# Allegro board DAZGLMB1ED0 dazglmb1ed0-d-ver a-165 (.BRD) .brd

Outline 387 x 183 mm; copper layers: TOP, SGND1, IN1, SGND2, IN2, SGND3, SVCC, IN3, SGND4, IN4, SGND5, IN5, SGND6, BOTTOM. Coordinates in mm from the lower left corner of the outline.

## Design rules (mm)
net group DFP-S5(3.1)W5.5(3.5)-T5: nets USBP1+_C USBP1-_C
net group DFP-S7(3.5)W5.5(3.5)-T1B: nets EDP_AUX#_C EDP_AUX_C
net group DFP-S20W5.5(3.5)-T1245B: nets XTAL24_IN XTAL24_OUT
net group W3.1-T12345B: nets H_PROCHOT# LCD_BL_PWM
net group W3.5-T1245B: nets 1080Q_8816AVSNS N35891538
net group W5.5-T12345B: nets BAT-V HP_JD#_EC
net group W80-T12345B: nets +5V_HDD VCC0P9_SVR
net group DFP-S4W5.5(5)-T1245B: nets VMA_CLK0 VMA_CLK0# VMA_CLK1 VMA_CLK1# VMA_WCK01 VMA_WCK01# VMA_WCK23 VMA_WCK23# VMA_WCK45 VMA_WCK45# VMA_WCK67 VMA_WCK67# VMB_CLK0 VMB_CLK0# VMB_CLK1 VMB_CLK1# VMB_WCK01 VMB_WCK01# VMB_WCK23 VMB_WCK23# VMB_WCK45 VMB_WCK45# VMB_WCK67 VMB_WCK67# VMC_CLK0 VMC_CLK0# VMC_CLK1 VMC_CLK1# VMC_WCK01 VMC_WCK01# VMC_WCK23 VMC_WCK23# VMC_WCK45 VMC_WCK45# VMC_WCK67 VMC_WCK67# VMD_CLK0 VMD_CLK0# VMD_CLK1 VMD_CLK1# VMD_WCK01 VMD_WCK01# VMD_WCK23 VMD_WCK23# VMD_WCK45 VMD_WCK45# VMD_WCK67 VMD_WCK67#
net group DFP-S5(3.1)W5.5(3.5)-T1245B: nets C_PCIE_RXN3_C C_PCIE_RXN4_C C_PCIE_RXP3_C C_PCIE_RXP4_C C_PEG_TX0 C_PEG_TX1 C_PEG_TX2 C_PEG_TX3 C_PEG_TX4 C_PEG_TX5 C_PEG_TX6 C_PEG_TX7 C_PEG_TX8 C_PEG_TX9 C_PEG_TX10 C_PEG_TX11 C_PEG_TX12 C_PEG_TX13 C_PEG_TX14 C_PEG_TX15 C_PEG_TX#0 C_PEG_TX#1 C_PEG_TX#2 C_PEG_TX#3 C_PEG_TX#4 C_PEG_TX#5 C_PEG_TX#6 C_PEG_TX#7 C_PEG_TX#8 C_PEG_TX#9 C_PEG_TX#10 C_PEG_TX#11 C_PEG_TX#12 C_PEG_TX#13 C_PEG_TX#14 C_PEG_TX#15 CLK_CPU_BCLKN CLK_CPU_BCLKP CLK_DPLL_NSCCLKN CLK_DPLL_NSCCLKP CLK_PCIE_LANN CLK_PCIE_LANP CLK_PCIE_NGFF1_N CLK_PCIE_NGFF1_N_Q CLK_PCIE_NGFF1_N_RE CLK_PCIE_NGFF1_P CLK_PCIE_NGFF1_P_Q CLK_PCIE_NGFF1_P_RE CLK_PCIE_NGFF2_N CLK_PCIE_NGFF2_N_R CLK_PCIE_NGFF2_N_RE CLK_PCIE_NGFF2_P CLK_PCIE_NGFF2_P_R CLK_PCIE_NGFF2_P_RE CLK_PCIE_TBTN CLK_PCIE_TBTP CLK_VGA_N CLK_VGA_P CPU_EDP_AUXN CPU_EDP_AUXP CPU_EDP_TXN0 CPU_EDP_TXN1 CPU_EDP_TXN2 CPU_EDP_TXN3 CPU_EDP_TXP0 CPU_EDP_TXP1 CPU_EDP_TXP2 CPU_EDP_TXP3 CPU_PCI_BCLKN CPU_PCI_BCLKP CPU_WIGIG_DP_AUXN CPU_WIGIG_DP_AUXP CPU_WIGIG_DP_ML0N CPU_WIGIG_DP_ML0P CPU_WIGIG_DP_ML1N CPU_WIGIG_DP_ML1P CPU_WIGIG_DP_ML2N CPU_WIGIG_DP_ML2P CPU_WIGIG_DP_ML3N CPU_WIGIG_DP_ML3P CPU_WIGIG_PCIE_RXN1 CPU_WIGIG_PCIE_RXP1 CPU_WIGIG_PCIE_TXN1 CPU_WIGIG_PCIE_TXP1 DMI_RXN0 DMI_RXN1 DMI_RXN2 DMI_RXN3 DMI_RXP0 DMI_RXP1 DMI_RXP2 DMI_RXP3 DMI_TXN0 DMI_TXN1 DMI_TXN2 DMI_TXN3 DMI_TXP0 DMI_TXP1 DMI_TXP2 DMI_TXP3 N32090895 N32090898 N35891440 N35891446 N35891554 N35891556 N35952409 N35952413 PCIE9_SATA_RXN PCIE9_SATA_RXN_C PCIE9_SATA_RXN_C_RE_C PCIE9_SATA_RXP PCIE9_SATA_RXP_C PCIE9_SATA_RXP_C_RE_C PCIE9_SATA_TXN PCIE9_SATA_TXN_C PCIE9_SATA_TXN_C_RE PCIE9_SATA_TXN_C_RE_C PCIE9_SATA_TXP PCIE9_SATA_TXP_C PCIE9_SATA_TXP_C_RE PCIE9_SATA_TXP_C_RE_C PCIE10_SATA_RXN PCIE10_SATA_RXN_C PCIE10_SATA_RXN_C_RE PCIE10_SATA_RXN_C_RE_C PCIE10_SATA_RXP PCIE10_SATA_RXP_C PCIE10_SATA_RXP_C_RE PCIE10_SATA_RXP_C_RE_C PCIE10_SATA_TXN PCIE10_SATA_TXN_C PCIE10_SATA_TXN_C_RE PCIE10_SATA_TXN_C_RE_C PCIE10_SATA_TXP PCIE10_SATA_TXP_C PCIE10_SATA_TXP_C_RE PCIE10_SATA_TXP_C_RE_C PCIE11_SATA_RXN PCIE11_SATA_RXN_C PCIE11_SATA_RXN_C_RE PCIE11_SATA_RXN_C_RE_C PCIE11_SATA_RXP PCIE11_SATA_RXP_C PCIE11_SATA_RXP_C_RE PCIE11_SATA_RXP_C_RE_C PCIE11_SATA_TXN PCIE11_SATA_TXN_C PCIE11_SATA_TXN_C_RE PCIE11_SATA_TXN_C_RE_C PCIE11_SATA_TXP PCIE11_SATA_TXP_C PCIE11_SATA_TXP_C_RE PCIE11_SATA_TXP_C_RE_C PCIE12_SATA_RXN PCIE12_SATA_RXN_C PCIE12_SATA_RXN_C_RE PCIE12_SATA_RXN_C_RE_C PCIE12_SATA_RXP PCIE12_SATA_RXP_C PCIE12_SATA_RXP_C_RE PCIE12_SATA_RXP_C_RE_C PCIE12_SATA_TXN PCIE12_SATA_TXN_C PCIE12_SATA_TXN_C_RE PCIE12_SATA_TXN_C_RE_C PCIE12_SATA_TXP PCIE12_SATA_TXP_C PCIE12_SATA_TXP_C_RE PCIE12_SATA_TXP_C_RE_C PCIE13_SATA_RXN PCIE13_SATA_RXN_C PCIE13_SATA_RXN_C_RE PCIE13_SATA_RXN_C_RE_C PCIE13_SATA_RXP PCIE13_SATA_RXP_C PCIE13_SATA_RXP_C_RE PCIE13_SATA_RXP_C_RE_C PCIE13_SATA_TXN PCIE13_SATA_TXN_C PCIE13_SATA_TXN_C_RE PCIE13_SATA_TXN_C_RE_C PCIE13_SATA_TXP PCIE13_SATA_TXP_C PCIE13_SATA_TXP_C_RE PCIE13_SATA_TXP_C_RE_C PCIE14_SATA_RXN PCIE14_SATA_RXN_C PCIE14_SATA_RXN_C_RE PCIE14_SATA_RXN_C_RE_C PCIE14_SATA_RXP PCIE14_SATA_RXP_C PCIE14_SATA_RXP_C_RE PCIE14_SATA_RXP_C_RE_C PCIE14_SATA_TXN PCIE14_SATA_TXN_C PCIE14_SATA_TXN_C_RE PCIE14_SATA_TXN_C_RE_C PCIE14_SATA_TXP PCIE14_SATA_TXP_C PCIE14_SATA_TXP_C_RE PCIE14_SATA_TXP_C_RE_C PCIE15_SATA_RXN PCIE15_SATA_RXN_C PCIE15_SATA_RXN_C_RE PCIE15_SATA_RXN_C_RE_C PCIE15_SATA_RXP PCIE15_SATA_RXP_C PCIE15_SATA_RXP_C_RE PCIE15_SATA_RXP_C_RE_C PCIE15_SATA_TXN PCIE15_SATA_TXN_C PCIE15_SATA_TXN_C_RE PCIE15_SATA_TXN_C_RE_C PCIE15_SATA_TXP PCIE15_SATA_TXP_C PCIE15_SATA_TXP_C_RE PCIE15_SATA_TXP_C_RE_C PCIE16_SATA_RXN PCIE16_SATA_RXN_C PCIE16_SATA_RXN_C_RE PCIE16_SATA_RXN_C_RE_C PCIE16_SATA_RXP PCIE16_SATA_RXP_C PCIE16_SATA_RXP_C_RE PCIE16_SATA_RXP_C_RE_C PCIE16_SATA_TXN PCIE16_SATA_TXN_C PCIE16_SATA_TXN_C_RE PCIE16_SATA_TXN_C_RE_C PCIE16_SATA_TXP PCIE16_SATA_TXP_C PCIE16_SATA_TXP_C_RE PCIE16_SATA_TXP_C_RE_C PCIE_RXN1_TBT_C PCIE_RXN2_TBT PCIE_RXN2_TBT_C PCIE_RXN3_TBT PCIE_RXN3_WLAN PCIE_RXN4_LAN PCIE_RXN4_LAN_R PCIE_RXN4_TBT PCIE_RXP1_TBT_C PCIE_RXP2_TBT PCIE_RXP2_TBT_C PCIE_RXP3_TBT PCIE_RXP3_WLAN PCIE_RXP4_LAN PCIE_RXP4_LAN_R PCIE_RXP4_TBT PCIE_TXN1_TBT PCIE_TXN1_TBT_C PCIE_TXN2_TBT PCIE_TXN2_TBT_C PCIE_TXN3_TBT PCIE_TXN3_TBT_C PCIE_TXN3_WLAN PCIE_TXN3_WLAN_C PCIE_TXN4_LAN PCIE_TXN4_LAN_C PCIE_TXN4_TBT PCIE_TXN4_TBT_C PCIE_TXP1_TBT PCIE_TXP1_TBT_C PCIE_TXP2_TBT PCIE_TXP2_TBT_C PCIE_TXP3_TBT PCIE_TXP3_TBT_C PCIE_TXP3_WLAN PCIE_TXP3_WLAN_C PCIE_TXP4_LAN PCIE_TXP4_LAN_C PCIE_TXP4_TBT PCIE_TXP4_TBT_C PEG_RXN0 PEG_RXN0_C PEG_RXN1 PEG_RXN1_C PEG_RXN2 PEG_RXN2_C PEG_RXN3 PEG_RXN3_C PEG_RXN4 PEG_RXN4_C PEG_RXN5 PEG_RXN5_C PEG_RXN6 PEG_RXN6_C PEG_RXN7 PEG_RXN7_C PEG_RXN8 PEG_RXN8_C PEG_RXN9 PEG_RXN9_C PEG_RXN10 PEG_RXN10_C PEG_RXN11 PEG_RXN11_C PEG_RXN12 PEG_RXN12_C PEG_RXN13 PEG_RXN13_C PEG_RXN14 PEG_RXN14_C PEG_RXN15 PEG_RXN15_C PEG_RXP0 PEG_RXP0_C PEG_RXP1 PEG_RXP1_C PEG_RXP2 PEG_RXP2_C PEG_RXP3 PEG_RXP3_C PEG_RXP4 PEG_RXP4_C PEG_RXP5 PEG_RXP5_C PEG_RXP6 PEG_RXP6_C PEG_RXP7 PEG_RXP7_C PEG_RXP8 PEG_RXP8_C PEG_RXP9 PEG_RXP9_C PEG_RXP10 PEG_RXP10_C PEG_RXP11 PEG_RXP11_C PEG_RXP12 PEG_RXP12_C PEG_RXP13 PEG_RXP13_C PEG_RXP14 PEG_RXP14_C PEG_RXP15 PEG_RXP15_C PEG_TXN0 PEG_TXN1 PEG_TXN2 PEG_TXN3 PEG_TXN4 PEG_TXN5 PEG_TXN6 PEG_TXN7 PEG_TXN8 PEG_TXN9 PEG_TXN10 PEG_TXN11 PEG_TXN12 PEG_TXN13 PEG_TXN14 PEG_TXN15 PEG_TXP0 PEG_TXP1 PEG_TXP2 PEG_TXP3 PEG_TXP4 PEG_TXP5 PEG_TXP6 PEG_TXP7 PEG_TXP8 PEG_TXP9 PEG_TXP10 PEG_TXP11 PEG_TXP12 PEG_TXP13 PEG_TXP14 PEG_TXP15 SATA_RXN0_C SATA_RXP0_C SATA_TXN0_C SATA_TXP0_C TBTA_USB2_D_N TBTA_USB2_D_N_B TBTA_USB2_D_N_T TBTA_USB2_D_P TBTA_USB2_D_P_B TBTA_USB2_D_P_T TBTA_USB2_N_B TBTA_USB2_N_T TBTA_USB2_P_B TBTA_USB2_P_T USB3_RXN1 USB3_RXN2 USB3_RXN2_C USB3_RXN2_C_RE USB3_RXN3 USB3_RXN3_C USB3_RXN3_C_RE USB3_RXN3_C_RE_R USB3_RXP1 USB3_RXP2 USB3_RXP2_C USB3_RXP2_C_RE USB3_RXP3 USB3_RXP3_C USB3_RXP3_C_RE USB3_RXP3_C_RE_R USB3_TXN1 USB3_TXN2 USB3_TXN2_C USB3_TXN2_C_RE USB3_TXN2_C_RE_C USB3_TXN2_C_RE_C_R USB3_TXN3 USB3_TXN3_C USB3_TXN3_C_RE USB3_TXN3_C_RE_C USB3_TXN3_C_RE_C_R USB3_TXP1 USB3_TXP2 USB3_TXP2_C USB3_TXP2_C_RE USB3_TXP2_C_RE_C USB3_TXP2_C_RE_C_R USB3_TXP3 USB3_TXP3_C USB3_TXP3_C_RE USB3_TXP3_C_RE_C USB3_TXP3_C_RE_C_R USBP1+ USBP1- USBP2+ USBP2- USBP3+ USBP3- USBP4+ USBP4- USBP5+ USBP5+_C USBP5- USBP5-_C USBP6+ USBP6- USBP7+ USBP7+_C USBP7- USBP7-_C USBP8+ USBP8+_C USBP8- USBP8-_C USBP9+ USBP9+_R USBP9- USBP9-_R WIGIG_DP_AUXN WIGIG_DP_AUXP WIGIG_PCIE_RXN1 WIGIG_PCIE_RXP1 WIGIG_PCIE_TXN1 WIGIG_PCIE_TXP1
net group DFP-S5W5.5-T: nets USB3_RXN1_R USB3_RXP1_R USB3_TXN1_C USB3_TXN1_R USB3_TXP1_C USB3_TXP1_R USBP1+_C_R USBP1-_C_R USBP2+_R USBP2-_R USBP3+_R USBP3-_R USBP4+_R USBP4-_R WIGIG_DP_ML0N WIGIG_DP_ML0P WIGIG_DP_ML1N WIGIG_DP_ML1P
net group DFP-S5W5.5-TB: nets CLK_PCIE_WIGIGN CLK_PCIE_WIGIGN_C CLK_PCIE_WIGIGP CLK_PCIE_WIGIGP_C CLK_PCIE_WLANN CLK_PCIE_WLANP WIGIG_DP_ML2N WIGIG_DP_ML2P WIGIG_DP_ML3N WIGIG_DP_ML3P
net group DFP-S6(3.1)W5.5(3.5)-T1245B: nets M_A_CLKN0 M_A_CLKN1 M_A_CLKP0 M_A_CLKP1 M_A_DQSN0 M_A_DQSN1 M_A_DQSN2 M_A_DQSN3 M_A_DQSN4 M_A_DQSN5 M_A_DQSN6 M_A_DQSN7 M_A_DQSP0 M_A_DQSP1 M_A_DQSP2 M_A_DQSP3 M_A_DQSP4 M_A_DQSP5 M_A_DQSP6 M_A_DQSP7 M_B_CLKN0 M_B_CLKN1 M_B_CLKP0 M_B_CLKP1 M_B_DQSN0 M_B_DQSN1 M_B_DQSN2 M_B_DQSN3 M_B_DQSN4 M_B_DQSN5 M_B_DQSN6 M_B_DQSN7 M_B_DQSP0 M_B_DQSP1 M_B_DQSP2 M_B_DQSP3 M_B_DQSP4 M_B_DQSP5 M_B_DQSP6 M_B_DQSP7
net group DFP-S7(3.5)W5.5(3.5)-T1245B: nets AUX_SRCN_TBT_C AUX_SRCP_TBT_C C_GPU_TBT_AUXN C_GPU_TBT_AUXP C_GPU_TBT_D0 C_GPU_TBT_D0# C_GPU_TBT_D1 C_GPU_TBT_D1# C_GPU_TBT_D2 C_GPU_TBT_D2# C_GPU_TBT_D3 C_GPU_TBT_D3# C_INT_DP_AUXN C_INT_DP_AUXP C_OUT_DP_TXN0 C_OUT_DP_TXN1 C_OUT_DP_TXN2 C_OUT_DP_TXN3 C_OUT_DP_TXP0 C_OUT_DP_TXP1 C_OUT_DP_TXP2 C_OUT_DP_TXP3 C_OUT_EDP_TXN0 C_OUT_EDP_TXN1 C_OUT_EDP_TXN2 C_OUT_EDP_TXN3 C_OUT_EDP_TXP0 C_OUT_EDP_TXP1 C_OUT_EDP_TXP2 C_OUT_EDP_TXP3 DDI1_TX0_DN DDI1_TX0_DN_C DDI1_TX0_DP DDI1_TX0_DP_C DDI1_TX1_DN DDI1_TX1_DN_C DDI1_TX1_DP DDI1_TX1_DP_C DDI1_TX2_DN DDI1_TX2_DN_C DDI1_TX2_DP DDI1_TX2_DP_C DDI1_TX3_DN DDI1_TX3_DN_C DDI1_TX3_DP DDI1_TX3_DP_C DP_D0 DP_D0# DP_D1 DP_D1# DP_D2 DP_D2# DP_D3 DP_D3# GPU_TBT_AUXN GPU_TBT_AUXP GPU_TBT_D0 GPU_TBT_D0# GPU_TBT_D1 GPU_TBT_D1# GPU_TBT_D2 GPU_TBT_D2# GPU_TBT_D3 GPU_TBT_D3# INT_DP_AUXN INT_DP_AUXP INT_EDP_AUXN INT_EDP_AUXP INT_EDP_TXN0 INT_EDP_TXN0_R INT_EDP_TXN1 INT_EDP_TXN1_R INT_EDP_TXN2 INT_EDP_TXN2_R INT_EDP_TXN3 INT_EDP_TXN3_R INT_EDP_TXP0 INT_EDP_TXP0_R INT_EDP_TXP1 INT_EDP_TXP1_R INT_EDP_TXP2 INT_EDP_TXP2_R INT_EDP_TXP3 INT_EDP_TXP3_R N31931449 N31931452 TBTA_AUX_N TBTA_AUX_P TBTA_DPSRC_AUX_N TBTA_DPSRC_AUX_P TBTA_LSRX TBTA_LSTX TBTA_SBU1 TBTA_SBU2 VGA_XTALIN VGA_XTALOUT
net group DFP-S7W4(3.5)-T1245B: nets GPU_CLK GPU_CLK# GPU_CLK#_C GPU_CLK_C GPU_D0 GPU_D0# GPU_D0#_C GPU_D0_C GPU_D1 GPU_D1# GPU_D1#_C GPU_D1_C GPU_D2 GPU_D2# GPU_D2#_C GPU_D2_C GPU_DDCCLK GPU_DDCDATA HDMI_SCLK HDMI_SDATA LAN_MX0+ LAN_MX0- LAN_MX1+ LAN_MX1- LAN_MX2+ LAN_MX2- LAN_MX3+ LAN_MX3- MDI_0+ MDI_0- MDI_1+ MDI_1- MDI_2+ MDI_2- MDI_3+ MDI_3- TX0_HDMI+ TX0_HDMI- TX1_HDMI+ TX1_HDMI- TX2_HDMI+ TX2_HDMI- TXC_HDMI+ TXC_HDMI-
net group DFP-S7W5.5-T: nets TBTA_CA2HD_1_N TBTA_CA2HD_1_P TBTA_HD2CA_0_N TBTA_HD2CA_0_P TBTA_TX0_N TBTA_TX0_P
net group DFP-S7W5.5-TB: nets EDP_TXN0_C EDP_TXN1_C EDP_TXN2_C EDP_TXN3_C EDP_TXP0_C EDP_TXP1_C EDP_TXP2_C EDP_TXP3_C TBTA_CA2HD_0_N TBTA_CA2HD_0_P TBTA_HD2CA_1_N TBTA_HD2CA_1_P TBTA_TX1_N TBTA_TX1_P
net group DFP-S15W5.5(3.5)-T1245B: nets RTC_X1 RTC_X2 TBT_XTL25_IN TBT_XTL25_OUT XTLI XTLO
net group W5-T1245B: nets FB_CAL_PD_VDDQ FB_CAL_PU_GND FB_CAL_TERM_GND
net group W5-T12345B: nets +VCC3P3_LC +VCCPGPPA +VCCPGPPEF +VCCPGPPG +VCCPRIM_3P3 CLK_VDD CPU_OPC_COMP CPU_OPCE_COMP CPU_OPCE_COMP2 EDP_RCOMP LED_B1_SYS LED_B1_SYS_R LED_B2_BAT LED_B2_BAT_R LED_G1_SYS LED_G1_SYS_R LED_G2_BAT LED_G2_BAT_R LED_G3_M_BTN LED_R1_SYS LED_R1_SYS_R LED_R2_BAT LED_R2_BAT_R PEG_COMP PW_VCC3_ANA_PCIE PW_VCC3_ANA_USB VCC0P9_LVR
net group W5.5(3.5)-T1245B: nets ACZ_BCLK ACZ_RST# ACZ_SDOUT ACZ_SYNC AUD_AZACPU_SCLK AUD_AZACPU_SCLK_R AUD_AZACPU_SDI AUD_AZACPU_SDI_L AUD_AZACPU_SDO AUD_AZACPU_SDO_R CLK_PCI_EC CLK_PCI_EC_R CLK_PCI_LPC CLK_PCI_LPC_R DDR4_DRAMRST# DMIC_CLK DMIC_CLK_C DMIC_DAT DMIC_DATA_C DRAM_RESET# H_CPU_SVIDALRT# H_CPU_SVIDDAT M_A_DQ0 M_A_DQ1 M_A_DQ2 M_A_DQ3 M_A_DQ4 M_A_DQ5 M_A_DQ6 M_A_DQ7 M_A_DQ8 M_A_DQ9 M_A_DQ10 M_A_DQ11 M_A_DQ12 M_A_DQ13 M_A_DQ14 M_A_DQ15 M_A_DQ16 M_A_DQ17 M_A_DQ18 M_A_DQ19 M_A_DQ20 M_A_DQ21 M_A_DQ22 M_A_DQ23 M_A_DQ24 M_A_DQ25 M_A_DQ26 M_A_DQ27 M_A_DQ28 M_A_DQ29 M_A_DQ30 M_A_DQ31 M_A_DQ32 M_A_DQ33 M_A_DQ34 M_A_DQ35 M_A_DQ36 M_A_DQ37 M_A_DQ38 M_A_DQ39 M_A_DQ40 M_A_DQ41 M_A_DQ42 M_A_DQ43 M_A_DQ44 M_A_DQ45 M_A_DQ46 M_A_DQ47 M_A_DQ48 M_A_DQ49 M_A_DQ50 M_A_DQ51 M_A_DQ52 M_A_DQ53 M_A_DQ54 M_A_DQ55 M_A_DQ56 M_A_DQ57 M_A_DQ58 M_A_DQ59 M_A_DQ60 M_A_DQ61 M_A_DQ62 M_A_DQ63 M_B_DQ0 M_B_DQ1 M_B_DQ2 M_B_DQ3 M_B_DQ4 M_B_DQ5 M_B_DQ6 M_B_DQ7 M_B_DQ8 M_B_DQ9 M_B_DQ10 M_B_DQ11 M_B_DQ12 M_B_DQ13 M_B_DQ14 M_B_DQ15 M_B_DQ16 M_B_DQ17 M_B_DQ18 M_B_DQ19 M_B_DQ20 M_B_DQ21 M_B_DQ22 M_B_DQ23 M_B_DQ24 M_B_DQ25 M_B_DQ26 M_B_DQ27 M_B_DQ28 M_B_DQ29 M_B_DQ30 M_B_DQ31 M_B_DQ32 M_B_DQ33 M_B_DQ34 M_B_DQ35 M_B_DQ36 M_B_DQ37 M_B_DQ38 M_B_DQ39 M_B_DQ40 M_B_DQ41 M_B_DQ42 M_B_DQ43 M_B_DQ44 M_B_DQ45 M_B_DQ46 M_B_DQ47 M_B_DQ48 M_B_DQ49 M_B_DQ50 M_B_DQ51 M_B_DQ52 M_B_DQ53 M_B_DQ54 M_B_DQ55 M_B_DQ56 M_B_DQ57 M_B_DQ58 M_B_DQ59 M_B_DQ60 M_B_DQ61 M_B_DQ62 M_B_DQ63 MP2949A_ALT# MP2949A_SCLK MP2949A_SDIO MP2949A_VORTN MP2949A_VORTNA MP2949A_VORTNB MP2949A_VOSEN MP2949A_VOSENA MP2949A_VOSENB N16771972 N31995611 N33795012 N33796046 N33796156 N35891568 PCH_AZ_CODEC_BITCLK PCH_AZ_CODEC_RST# PCH_AZ_CODEC_SDIN0 PCH_AZ_CODEC_SDOUT PCH_AZ_CODEC_SYNC PCIE_CLKREQ1# PCIE_CLKREQ2# PCIE_CLKREQ3# PCIE_CLKREQ4# PCIE_CLKREQ7# PCIE_CLKREQ8# PCIE_CLKREQ_LAN# PCIE_CLKREQ_NGFF1# PCIE_CLKREQ_NGFF2# PCIE_CLKREQ_TBT# PCIE_CLKREQ_TBT#_C PCIE_CLKREQ_VGA# PCIE_CLKREQ_WIGIG# PCIE_CLKREQ_WLAN# PCIE_REQ_LAN#_R RTC_RST# SRTC_RST# VCCIO_VCCSENSE VCCSA_VCCSENSE VCCSA_VSSSENSE VCCSENSE VGT_VCCSENSE VGT_VSSSENSE VR_SVID_ALERT# VR_SVID_CLK VR_SVID_CLK_R VR_SVID_DATA VSSIO_VSSSENSE VSSSENSE WLAN_CLKREQ# XCLK_RBIAS
net group W5.5(3.5: nets 2ND_MBCLK 2ND_MBCLK_THM 2ND_MBDATA 2ND_MBDATA_THM 3ND_MBCLK 3ND_MBCLK_P_KB 3ND_MBCLK_UIF 3ND_MBDATA 3ND_MBDATA_P_KB 3ND_MBDATA_UIF 1006_I2C_SCL 1006_I2C_SDA 1006_I2S_BCLK 1006_I2S_LRCK 1006_I2S_MCLK 1006_I2S_OUT ACE_I2C_SCL2 ACE_I2C_SDA2 BL# BL_ON BLON_EN BLONCON CATERR# CFG_RCOMP CPU_2_PCH_TRIG CPU_2_PCH_TRIG_R CPU_PLTRST#R CPU_THERMDA CPU_THERMDC DDPB_CLK DDPB_DATA DDPC_CLK DDPC_DATA DNBSWON# DP_HPD_PCH DP_HPD_PCH_R EC_PECI EC_PECR_R EC_PWROK EC_PWROK_R EDP_HPD_GPU EDP_HPD_R EDP_HPD_RR EDP_VDD_EN FRM_LCK# FRM_LCK#_PANEL GFX_SCL GFX_SDA GPIO27_IFPE_HPD_Q GPUT_CLK GPUT_DATA H_PM_DOWN H_PM_DOWN_R H_PROCHOT#_R HDMI_HPD HDMI_HPD_PCH HOLD#_7 I2C0_SCL I2C0_SDA I2C1_SCL I2C1_SDA I2C_TP_SCL_R I2C_TP_SDA_R I2CC_SCL_GFX I2CC_SCL_IPC I2CC_SDA_GFX I2CC_SDA_IPC LCD_BLEN LCD_VDD LPC_LAD0 LPC_LAD0_C LPC_LAD1 LPC_LAD1_C LPC_LAD2 LPC_LAD2_C LPC_LAD3 LPC_LAD3_C LPC_LFRAME# MB_THRMTRIP# MBCLK MBDATA MP2949A_VRHOT# N30641967 PCH_2_CPU_TRIG PCH_2_CPU_TRIG_R PCH_BLON_EC PCH_BRIGHT PCH_DISP_ON PCH_DPST_PWM PCH_LVDS_BLON PCH_PECI PCH_PWROK PCH_RSMRST# PCH_SPI_CLK PCH_SPI_CLK_EC PCH_SPI_CS0# PCH_SPI_IO2 PCH_SPI_IO3 PCH_SPI_SI PCH_SPI_SI_EC PCH_SPI_SO PCH_SPI_SO_EC PCH_THRMTRIP_R# PCIE_LAN_WAKE#_R PCIE_WAKE# PCIE_WAKE#_TBT PM_SYNC PM_SYNC_R PM_THRMTRIP# PROCHOT_EC PROCPWRGD ROM_CS ROM_CS_R ROM_SCLK ROM_SCLK_R ROM_SI ROM_SI_R ROM_SO RSMRST# SIO_RCIN# SM_INTRUDER# SMB_ME0_CLK SMB_ME0_DAT SMB_ME1_CLK SMB_ME1_DAT SMB_ME2_CLK SMB_ME2_DAT SMB_ME3_CLK SMB_ME3_DAT SMB_ME4_CLK SMB_ME4_DAT SMB_PCH_CLK SMB_PCH_DAT SMB_RUN_CLK SMB_RUN_DAT SPI_CLK SPI_CS0# SPI_CS0#_UR_ME SPI_HOLD_IO3 SPI_SI SPI_SO SPI_WP_IO2 SYS_PWROK SYS_PWROK_R SYS_RESET# TBT_EE_CLK TBT_EE_CS_N TBT_EE_DI TBT_EE_DO TBT_EE_WP_N TBT_I2C_SCL TBT_I2C_SDA TBT_SPI_HOLD# TPCLK TPDATA USB2_COMP USB_OC0# VCCST_PWRGD VCCST_PWRGD_R WLAN_WAKE_R# WP#_3
net group W5.5-B: nets TBT1_PCIE_RBIAS TBT_RBIAS TBT_RSENSE
net group W6-T12345B: nets +VIN TBTA_LDO_BMC VCC1V8A_TBTA_LDO VCC1V8D_TBTA_LDO VCC3V3_FLASH VCC3V3_TBTA_SX
net group W7-T12345B: nets +3V_DVDD_IO +3V_EDP +3V_TYPEC_DP +3VPCU_EC +601_VCC +602_VCC +603_VCC +604_VCC AVDDL CAP-
net group W8-T1245B: nets 1080Q_FBRTN CORE_PLLVDD FBA_PLL_AVDD FBVDDQ_SENSE N25329172 TBTA_CC1 TBTA_CC2 VGPU_CORE_SENSE VSS_GPU_SENSE
net group W8-T12345B: nets +1.2VSUS +1.8V +1.8V_AON +3V +3V_DEEP_SUS +3V_DVDD +3V_S5 +3V_U3_R +3VPCU +3VPCU_ECPLL +5V_PVDD +5V_TOBII +5VA +A3VPCU +TPVDD AVDDH AVDDVCO CAP+ CCD_PWR DVDDL ECAGND HP-L2 HP-R2 LANVCC MIC2-VREFO-L MIC2-VREFO-R NVVDD USBPWR2 USBPWR3 VCC0P9_DP VCC0P9_PCIE
net group W8.5(5.5)-T1245B: nets FBA_CMD0 FBA_CMD1 FBA_CMD2 FBA_CMD3 FBA_CMD4 FBA_CMD5 FBA_CMD6 FBA_CMD7 FBA_CMD8 FBA_CMD9 FBA_CMD10 FBA_CMD11 FBA_CMD12 FBA_CMD13 FBA_CMD14 FBA_CMD15 FBA_CMD16 FBA_CMD17 FBA_CMD18 FBA_CMD19 FBA_CMD20 FBA_CMD21 FBA_CMD22 FBA_CMD23 FBA_CMD24 FBA_CMD25 FBA_CMD26 FBA_CMD27 FBA_CMD28 FBA_CMD29 FBA_CMD30 FBA_CMD31 FBA_DBI0 FBA_DBI1 FBA_DBI2 FBA_DBI3 FBA_DBI4 FBA_DBI5 FBA_DBI6 FBA_DBI7 FBA_EDC0 FBA_EDC1 FBA_EDC2 FBA_EDC3 FBA_EDC4 FBA_EDC5 FBA_EDC6 FBA_EDC7 FBB_CMD0 FBB_CMD1 FBB_CMD2 FBB_CMD3 FBB_CMD4 FBB_CMD5 FBB_CMD6 FBB_CMD7 FBB_CMD8 FBB_CMD9 FBB_CMD10 FBB_CMD11 FBB_CMD12 FBB_CMD13 FBB_CMD14 FBB_CMD15 FBB_CMD16 FBB_CMD17 FBB_CMD18 FBB_CMD19 FBB_CMD20 FBB_CMD21 FBB_CMD22 FBB_CMD23 FBB_CMD24 FBB_CMD25 FBB_CMD26 FBB_CMD27 FBB_CMD28 FBB_CMD29 FBB_CMD30 FBB_CMD31 FBB_DBI0 FBB_DBI1 FBB_DBI2 FBB_DBI3 FBB_DBI4 FBB_DBI5 FBB_DBI6 FBB_DBI7 FBB_EDC0 FBB_EDC1 FBB_EDC2 FBB_EDC3 FBB_EDC4 FBB_EDC5 FBB_EDC6 FBB_EDC7 FBC_CMD0 FBC_CMD1 FBC_CMD2 FBC_CMD3 FBC_CMD4 FBC_CMD5 FBC_CMD6 FBC_CMD7 FBC_CMD8 FBC_CMD9 FBC_CMD10 FBC_CMD11 FBC_CMD12 FBC_CMD13 FBC_CMD14 FBC_CMD15 FBC_CMD16 FBC_CMD17 FBC_CMD18 FBC_CMD19 FBC_CMD20 FBC_CMD21 FBC_CMD22 FBC_CMD23 FBC_CMD24 FBC_CMD25 FBC_CMD26 FBC_CMD27 FBC_CMD28 FBC_CMD29 FBC_CMD30 FBC_CMD31 FBC_DBI0 FBC_DBI1 FBC_DBI2 FBC_DBI3 FBC_DBI4 FBC_DBI5 FBC_DBI6 FBC_DBI7 FBC_EDC0 FBC_EDC1 FBC_EDC2 FBC_EDC3 FBC_EDC4 FBC_EDC5 FBC_EDC6 FBC_EDC7 FBD_CMD0 FBD_CMD1 FBD_CMD2 FBD_CMD3 FBD_CMD4 FBD_CMD5 FBD_CMD6 FBD_CMD7 FBD_CMD8 FBD_CMD9 FBD_CMD10 FBD_CMD11 FBD_CMD12 FBD_CMD13 FBD_CMD14 FBD_CMD15 FBD_CMD16 FBD_CMD17 FBD_CMD18 FBD_CMD19 FBD_CMD20 FBD_CMD21 FBD_CMD22 FBD_CMD23 FBD_CMD24 FBD_CMD25 FBD_CMD26 FBD_CMD27 FBD_CMD28 FBD_CMD29 FBD_CMD30 FBD_CMD31 FBD_DBI0 FBD_DBI1 FBD_DBI2 FBD_DBI3 FBD_DBI4 FBD_DBI5 FBD_DBI6 FBD_DBI7 FBD_EDC0 FBD_EDC1 FBD_EDC2 FBD_EDC3 FBD_EDC4 FBD_EDC5 FBD_EDC6 FBD_EDC7 M_A_A0 M_A_A1 M_A_A2 M_A_A3 M_A_A4 M_A_A5 M_A_A6 M_A_A7 M_A_A8 M_A_A9 M_A_A10 M_A_A11 M_A_A12 M_A_A13 M_A_ACT# M_A_ALERT# M_A_BA#0 M_A_BA#1 M_A_BG#0 M_A_BG#1 M_A_CAS# M_A_CKE0 M_A_CKE1 M_A_CS#0 M_A_CS#1 M_A_ODT0_CPU M_A_ODT1_CPU M_A_PARITY M_A_RAS# M_A_WE# M_B_A0 M_B_A1 M_B_A2 M_B_A3 M_B_A4 M_B_A5 M_B_A6 M_B_A7 M_B_A8 M_B_A9 M_B_A10 M_B_A11 M_B_A12 M_B_A13 M_B_ACT# M_B_ALERT# M_B_BA#0 M_B_BA#1 M_B_BG#0 M_B_BG#1 M_B_CAS# M_B_CKE0 M_B_CKE1 M_B_CS#0 M_B_CS#1 M_B_ODT0_CPU M_B_ODT1_CPU M_B_PARITY M_B_RAS# M_B_WE# VMA_DQ0 VMA_DQ1 VMA_DQ2 VMA_DQ3 VMA_DQ4 VMA_DQ5 VMA_DQ6 VMA_DQ7 VMA_DQ8 VMA_DQ9 VMA_DQ10 VMA_DQ11 VMA_DQ12 VMA_DQ13 VMA_DQ14 VMA_DQ15 VMA_DQ16 VMA_DQ17 VMA_DQ18 VMA_DQ19 VMA_DQ20 VMA_DQ21 VMA_DQ22 VMA_DQ23 VMA_DQ24 VMA_DQ25 VMA_DQ26 VMA_DQ27 VMA_DQ28 VMA_DQ29 VMA_DQ30 VMA_DQ31 VMA_DQ32 VMA_DQ33 VMA_DQ34 VMA_DQ35 VMA_DQ36 VMA_DQ37 VMA_DQ38 VMA_DQ39 VMA_DQ40 VMA_DQ41 VMA_DQ42 VMA_DQ43 VMA_DQ44 VMA_DQ45 VMA_DQ46 VMA_DQ47 VMA_DQ48 VMA_DQ49 VMA_DQ50 VMA_DQ51 VMA_DQ52 VMA_DQ53 VMA_DQ54 VMA_DQ55 VMA_DQ56 VMA_DQ57 VMA_DQ58 VMA_DQ59 VMA_DQ60 VMA_DQ61 VMA_DQ62 VMA_DQ63 VMB_DQ0 VMB_DQ1 VMB_DQ2 VMB_DQ3 VMB_DQ4 VMB_DQ5 VMB_DQ6 VMB_DQ7 VMB_DQ8 VMB_DQ9 VMB_DQ10 VMB_DQ11 VMB_DQ12 VMB_DQ13 VMB_DQ14 VMB_DQ15 VMB_DQ16 VMB_DQ17 VMB_DQ18 VMB_DQ19 VMB_DQ20 VMB_DQ21 VMB_DQ22 VMB_DQ23 VMB_DQ24 VMB_DQ25 VMB_DQ26 VMB_DQ27 VMB_DQ28 VMB_DQ29 VMB_DQ30 VMB_DQ31 VMB_DQ32 VMB_DQ33 VMB_DQ34 VMB_DQ35 VMB_DQ36 VMB_DQ37 VMB_DQ38 VMB_DQ39 VMB_DQ40 VMB_DQ41 VMB_DQ42 VMB_DQ43 VMB_DQ44 VMB_DQ45 VMB_DQ46 VMB_DQ47 VMB_DQ48 VMB_DQ49 VMB_DQ50 VMB_DQ51 VMB_DQ52 VMB_DQ53 VMB_DQ54 VMB_DQ55 VMB_DQ56 VMB_DQ57 VMB_DQ58 VMB_DQ59 VMB_DQ60 VMB_DQ61 VMB_DQ62 VMB_DQ63 VMC_DQ0 VMC_DQ1 VMC_DQ2 VMC_DQ3 VMC_DQ4 VMC_DQ5 VMC_DQ6 VMC_DQ7 VMC_DQ8 VMC_DQ9 VMC_DQ10 VMC_DQ11 VMC_DQ12 VMC_DQ13 VMC_DQ14 VMC_DQ15 VMC_DQ16 VMC_DQ17 VMC_DQ18 VMC_DQ19 VMC_DQ20 VMC_DQ21 VMC_DQ22 VMC_DQ23 VMC_DQ24 VMC_DQ25 VMC_DQ26 VMC_DQ27 VMC_DQ28 VMC_DQ29 VMC_DQ30 VMC_DQ31 VMC_DQ32 VMC_DQ33 VMC_DQ34 VMC_DQ35 VMC_DQ36 VMC_DQ37 VMC_DQ38 VMC_DQ39 VMC_DQ40 VMC_DQ41 VMC_DQ42 VMC_DQ43 VMC_DQ44 VMC_DQ45 VMC_DQ46 VMC_DQ47 VMC_DQ48 VMC_DQ49 VMC_DQ50 VMC_DQ51 VMC_DQ52 VMC_DQ53 VMC_DQ54 VMC_DQ55 VMC_DQ56 VMC_DQ57 VMC_DQ58 VMC_DQ59 VMC_DQ60 VMC_DQ61 VMC_DQ62 VMC_DQ63 VMD_DQ0 VMD_DQ1 VMD_DQ2 VMD_DQ3 VMD_DQ4 VMD_DQ5 VMD_DQ6 VMD_DQ7 VMD_DQ8 VMD_DQ9 VMD_DQ10 VMD_DQ11 VMD_DQ12 VMD_DQ13 VMD_DQ14 VMD_DQ15 VMD_DQ16 VMD_DQ17 VMD_DQ18 VMD_DQ19 VMD_DQ20 VMD_DQ21 VMD_DQ22 VMD_DQ23 VMD_DQ24 VMD_DQ25 VMD_DQ26 VMD_DQ27 VMD_DQ28 VMD_DQ29 VMD_DQ30 VMD_DQ31 VMD_DQ32 VMD_DQ33 VMD_DQ34 VMD_DQ35 VMD_DQ36 VMD_DQ37 VMD_DQ38 VMD_DQ39 VMD_DQ40 VMD_DQ41 VMD_DQ42 VMD_DQ43 VMD_DQ44 VMD_DQ45 VMD_DQ46 VMD_DQ47 VMD_DQ48 VMD_DQ49 VMD_DQ50 VMD_DQ51 VMD_DQ52 VMD_DQ53 VMD_DQ54 VMD_DQ55 VMD_DQ56 VMD_DQ57 VMD_DQ58 VMD_DQ59 VMD_DQ60 VMD_DQ61 VMD_DQ62 VMD_DQ63
net group W9.84-T12345B: nets FBVDDQ_MEM
net group W10-T1245B: nets DDR_VTT
net group W10-T12345B: nets +1.8V_MAIN +1V_SUS +3V_KB_P +3V_LDO_EC +3V_RTC +5V +5VPCU +5VPD +VCC3P3_S0 +VCC3P3_SX +VCCAPLLEBB +VCCCLK2 +VCCDSW3P3 +VCCPCIE3PLL_1P0 +VCCPGPPBCH +VCCPLL +VCCPLL_OC +VCCPRIM_1.0V_AC17 +VCCPRIM_1.0V_AJ20_AD15 +VCCPRIM_1.0V_AL22 +VIN_VGACORE HP-L3 HP-R3 HPOUT_L2 HPOUT_R2 LED_A_B LED_A_G LED_A_R LED_B4_P_BTN LED_B5_GPU_FAN LED_B5_GPU_FAN_R LED_B_B LED_B_G LED_B_R LED_C_B LED_C_G LED_C_R LED_D_B LED_D_G LED_D_R LED_G4_P_BTN LED_G5_GPU_FAN LED_G5_GPU_FAN_R LED_R4_P_BTN LED_R5_GPU_FAN LED_R5_GPU_FAN_R LX MIC_VCC_1.8V PCIECOMP_N PCIECOMP_P SM_RCOMP_2 TS_PWR TYPEC_VBUS VCC0P9_USB
net group W12-T12345B: nets +3V3PD +5V_TP_RGB SM_RCOMP_0 SM_RCOMP_1
net group W15-T12345B: nets +3V_AR +5V_KB_M +VCCAMPHYPLL_1P0 +VDDQC MIC_JD# VCC0P9_CIO
net group W16-T12345B: nets FBA_VREFC FBB_VREFC FBC_VREFC FBD_VREFC
net group W20-T12345B: nets +1V_GFX +1V_S5 +2.5V +2.5VSUS +3V_EC +3V_MINIDP +5V_FAN1 +5V_FAN2 +5V_GPU_LED +5V_HDMIC +5V_KB_LED +5V_S5 +12V_PANEL +VCC_CORE +VCC_GT +VCC_SA +VCCAMPHY_1P0 +VCCIO +VCCPRIM_1.0V_AJ20 +VCCPRIM_1.0V_AJ20_AA23 +VDDQ +WL_VDD LCDVCC LCDVCC_R LINLVP LIP LVN RINRVP RIP RVN SM_VREF SMDDR_VREF_DQ0_M3 SMDDR_VREF_DQ1_M3 SPKLN_L SPKLP_L SPKRN_L SPKRP_L VREF_CA_DIMM0 VREF_CA_DIMM1
net group W24-T12345B: nets LAN_MCT0 LAN_MCT1 LAN_MCT2 LAN_MCT3
net group W30-T12345B: nets TERM9
net group W40-T12345B: nets +3V_SSD1 +3V_SSD2 L_SPK+ L_SPK- MIC2-L MIC2-L_1 MIC2-R MIC2-R_1 R_SPK+ R_SPK- USBPWR0
net group W80-T: nets VCC0P9_SVR_IND

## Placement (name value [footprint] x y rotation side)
C85  0.1u/10V_2  [C0201]  272.05 125.7 90 top
C194  10u/6.3V_4  [C0402_2]  252.62 119.98 0 bottom
C202  1u/6.3V_2  [C0201]  258.72 114.7 180 bottom
C216  *220p/50V_4  [C0402]  325.27 77.44 90 top
C218  *220p/50V_4  [C0402]  326.38 77.44 90 top
C260  1u/6.3V_2  [C0201]  228.9 126.81 180 bottom
C273  1u/6.3V_2  [C0201]  227.73 126.51 270 bottom
C417  0.1u/10V_2  [C0201]  211.35 103.85 270 bottom
C420  *0.1u/10V_2  [C0201]  211.55 98.87 0 bottom
C574  10u/6.3V_4  [C0402_2]  190.95 55.49 0 bottom
C669  *HDD@47u/6.3V_8  [C0805]  68.52 34.41 180 top
C670  HDD@10u/6.3V_4  [C0402_2]  68.02 32.2 90 bottom
C675  HDD@0.01u/50V_4  [C0402]  70.38 32.3 90 bottom
C680  *HDD@0.1u/16V_4  [C0402]  69.27 32.31 90 bottom
C689  *HDD@0.1u/16V_4  [C0402]  67.84 35.4 270 bottom
C718  10u/6.3V_4  [C0402_2]  358.67 60.93 90 top
C721  1u/6.3V_2  [C0201]  347.85 52.8 180 bottom
C755  0.1u/10V_2  [C0201]  272.84 131.26 180 top
C767  10u/6.3V_4  [C0402_2]  233.95 117.9 180 bottom
C802  *47p/25V_2  [C0201]  269.13 131.79 0 top
C807  47p/25V_2  [C0201]  269.26 127.55 0 top
C812  *0.1u/10V_2  [C0201]  213.68 101.87 270 bottom
C853  *0.1u/10V_2  [C0201]  175.41 68.04 0 top
C887  *180p/50V_4  [C0402]  191.69 60.52 180 bottom
C889  1u/6.3V_2  [C0201]  178.81 61.43 270 bottom
C890  *10p/50V_4  [C0402]  183.66 60.65 0 bottom
C891  0.1u/10V_2  [C0201]  177.95 61.28 90 bottom
C892  0.1u/10V_2  [C0201]  176.3 62.07 90 top
C897  0.1u/10V_2  [C0201]  188.62 69.56 270 top
C961  0.47u/25V_4  [C0402]  382.54 41.75 90 bottom
C963  *22u/25V_8  [C0805]  369.21 36.16 0 top
C1194  0.22u/6.3V_2  [C0201]  219.86 127.85 0 top
C13391  0.22u/6.3V_2  [C0201]  357.91 51.4 180 bottom
C13393  47u/6.3V_6  [C0603]  358.01 62.7 180 top
C13512  10p/50V_4  [C0402]  355.37 45.33 0 top
C13548  0.1u/10V_2  [C0201]  341.78 56.1 180 top
C93687  0.1u/10V_2  [C0201]  330.32 58.51 0 top
C93696  10u/6.3V_4  [C0402_2]  330.6 60.42 90 top
C94044  1u/6.3V_2  [C0201]  350.41 51.02 90 bottom
C94051  *SUB@680p/50V_4  [C0402]  38.37 36.75 270 bottom
C94182  0.1u/10V_2  [C0201]  338.2 68.67 180 bottom
C94248  0.22u/6.3V_2  [C0201]  219.86 127.09 0 top
C94249  0.22u/6.3V_2  [C0201]  219.98 125.44 0 top
C94250  0.22u/6.3V_2  [C0201]  219.98 126.2 0 top
C94251  0.22u/6.3V_2  [C0201]  218.21 125.7 0 top
C94252  0.22u/6.3V_2  [C0201]  218.21 124.93 0 top
C94253  0.22u/6.3V_2  [C0201]  218.59 123.41 0 top
C94254  0.22u/6.3V_2  [C0201]  218.59 124.17 0 top
C94255  0.22u/6.3V_2  [C0201]  217.19 123.41 0 top
C94256  0.22u/6.3V_2  [C0201]  217.19 122.65 0 top
C94257  0.22u/6.3V_2  [C0201]  217.19 121.12 0 top
C94258  0.22u/6.3V_2  [C0201]  217.19 121.89 0 top
C94259  0.22u/6.3V_2  [C0201]  218.49 121 0 top
C94260  0.22u/6.3V_2  [C0201]  218.49 120.23 0 top
C94261  0.22u/6.3V_2  [C0201]  218.49 118.71 0 top
C94262  0.22u/6.3V_2  [C0201]  218.49 119.47 0 top
C94263  0.22u/6.3V_2  [C0201]  218.46 117.19 0 top
C94264  0.22u/6.3V_2  [C0201]  218.46 117.95 0 top
C94265  0.22u/6.3V_2  [C0201]  215.67 116.93 0 top
C94266  0.22u/6.3V_2  [C0201]  215.67 117.69 0 top
C94267  0.22u/6.3V_2  [C0201]  216.68 115.41 270 top
C94268  0.22u/6.3V_2  [C0201]  217.44 115.41 270 top
C94269  0.22u/6.3V_2  [C0201]  215.54 114.9 0 top
C94270  0.22u/6.3V_2  [C0201]  215.54 115.66 0 top
C94271  0.22u/6.3V_2  [C0201]  215.54 113.38 0 top
C94272  0.22u/6.3V_2  [C0201]  215.54 114.14 0 top
C94273  0.22u/6.3V_2  [C0201]  215.54 111.85 0 top
C94274  0.22u/6.3V_2  [C0201]  215.54 112.61 0 top
C94275  0.22u/6.3V_2  [C0201]  214.27 110.94 0 top
C94276  0.22u/6.3V_2  [C0201]  214.27 111.7 0 top
C94277  0.22u/6.3V_2  [C0201]  214.29 109.36 0 top
C94278  0.22u/6.3V_2  [C0201]  214.29 110.13 0 top
C94279  1u/6.3V_2  [C0201]  249.96 114.34 0 bottom
C94280  1u/6.3V_2  [C0201]  255.93 119.85 0 bottom
C94281  1u/6.3V_2  [C0201]  258.72 116.81 180 bottom
C94282  1u/6.3V_2  [C0201]  252.62 114.39 180 bottom
C94283  1u/6.3V_2  [C0201]  258.72 119.09 180 bottom
C94284  1u/6.3V_2  [C0201]  255.93 114.85 0 bottom
C94285  1u/6.3V_2  [C0201]  255.93 118.33 0 bottom
C94286  1u/6.3V_2  [C0201]  258.72 112.61 180 bottom
C94287  1u/6.3V_2  [C0201]  258.72 118.33 180 bottom
C94288  1u/6.3V_2  [C0201]  255.93 114.09 0 bottom
C94289  1u/6.3V_2  [C0201]  255.93 119.09 0 bottom
C94290  1u/6.3V_2  [C0201]  258.72 113.99 180 bottom
C94291  1u/6.3V_2  [C0201]  258.72 119.85 180 bottom
C94292  1u/6.3V_2  [C0201]  249.96 115.1 0 bottom
C94293  1u/6.3V_2  [C0201]  249.58 126.2 0 bottom
C94294  1u/6.3V_2  [C0201]  252.62 115.15 180 bottom
C94295  1u/6.3V_2  [C0201]  258.72 117.57 180 bottom
C94296  1u/6.3V_2  [C0201]  258.72 120.62 180 bottom
C94297  1u/6.3V_2  [C0201]  255.93 120.62 0 bottom
C94298  1u/6.3V_2  [C0201]  252.62 126.08 180 bottom
C94299  10u/6.3V_4  [C0402_2]  258.67 115.66 0 bottom
C94300  10u/6.3V_4  [C0402_2]  255.93 123.41 180 bottom
C94301  10u/6.3V_4  [C0402_2]  255.93 121.76 180 bottom
C94302  10u/6.3V_4  [C0402_2]  249.58 125.19 180 bottom
C94303  10u/6.3V_4  [C0402_2]  252.62 121.25 0 bottom
C94304  10u/6.3V_4  [C0402_2]  255.93 125.06 180 bottom
C94305  10u/6.3V_4  [C0402_2]  258.72 125.06 0 bottom
C94306  10u/6.3V_4  [C0402_2]  252.62 125.06 0 bottom
C94307  10u/6.3V_4  [C0402_2]  252.62 116.17 0 bottom
C94308  10u/6.3V_4  [C0402_2]  252.6 117.49 0 bottom
C94309  10u/6.3V_4  [C0402_2]  252.62 122.52 0 bottom
C94310  10u/6.3V_4  [C0402_2]  255.93 117.19 180 bottom
C94311  10u/6.3V_4  [C0402_2]  255.93 115.92 180 bottom
C94317  10u/6.3V_4  [C0402_2]  252.62 118.71 0 bottom
C94318  10u/6.3V_4  [C0402_2]  252.62 123.79 0 bottom
C94319  22u/6.3V_6  [C0603]  249.58 122.17 180 bottom
C94320  22u/6.3V_6  [C0603]  249.58 117.69 180 bottom
C94321  22u/6.3V_6  [C0603]  258.72 123.41 0 bottom
C94322  22u/6.3V_6  [C0603]  258.72 121.76 0 bottom
C94323  22u/6.3V_6  [C0603]  249.58 120.74 180 bottom
C94324  22u/6.3V_6  [C0603]  249.58 119.22 180 bottom
C94325  22u/6.3V_6  [C0603]  249.58 123.84 180 bottom
C94326  22u/6.3V_6  [C0603]  249.58 116.17 180 bottom
C94384  10u/6.3V_4  [C0402_2]  236.11 126.71 0 bottom
C94385  10u/6.3V_4  [C0402_2]  236.11 125.44 0 bottom
C94386  10u/6.3V_4  [C0402_2]  236.11 122.9 0 bottom
C94387  10u/6.3V_4  [C0402_2]  241.32 117.34 0 bottom
C94388  10u/6.3V_4  [C0402_2]  236.11 124.17 0 bottom
C94389  10u/6.3V_4  [C0402_2]  238.78 113.5 180 bottom
C94390  10u/6.3V_4  [C0402_2]  233.95 121.71 180 bottom
C94391  10u/6.3V_4  [C0402_2]  233.95 120.44 180 bottom
C94392  10u/6.3V_4  [C0402_2]  233.95 119.22 180 bottom
C94393  10u/6.3V_4  [C0402_2]  233.95 122.98 180 bottom
C94394  10u/6.3V_4  [C0402_2]  233.95 126.71 180 bottom
C94395  10u/6.3V_4  [C0402_2]  236.11 121.63 0 bottom
C94396  10u/6.3V_4  [C0402_2]  236.11 119.17 0 bottom
C94397  10u/6.3V_4  [C0402_2]  236.11 116.68 0 bottom
C94398  10u/6.3V_4  [C0402_2]  236.11 120.39 0 bottom
C94399  10u/6.3V_4  [C0402_2]  233.95 124.17 180 bottom
C94400  10u/6.3V_4  [C0402_2]  241.32 116.07 0 bottom
C94401  10u/6.3V_4  [C0402_2]  241.32 113.58 0 bottom
C94402  10u/6.3V_4  [C0402_2]  241.32 118.61 0 bottom
C94403  10u/6.3V_4  [C0402_2]  233.95 116.6 180 bottom
C94404  10u/6.3V_4  [C0402_2]  234.59 114.14 180 bottom
C94405  10u/6.3V_4  [C0402_2]  233.95 125.44 180 bottom
C94406  10u/6.3V_4  [C0402_2]  234.59 112.87 180 bottom
C94407  10u/6.3V_4  [C0402_2]  236.11 117.95 0 bottom
C94408  10u/6.3V_4  [C0402_2]  236.11 115.41 0 bottom
C94409  10u/6.3V_4  [C0402_2]  233.95 115.33 180 bottom
C94410  10u/6.3V_4  [C0402_2]  241.32 114.8 0 bottom
C94411  22u/6.3V_6  [C0603]  238.78 122.52 180 bottom
C94412  22u/6.3V_6  [C0603]  238.75 125.57 180 bottom
C94413  22u/6.3V_6  [C0603]  238.78 121 180 bottom
C94414  22u/6.3V_6  [C0603]  238.78 116.42 180 bottom
C94415  22u/6.3V_6  [C0603]  238.78 114.9 180 bottom
C94416  22u/6.3V_6  [C0603]  238.78 117.95 180 bottom
C94417  22u/6.3V_6  [C0603]  238.75 124.04 180 bottom
C94418  22u/6.3V_6  [C0603]  238.78 119.47 180 bottom
C94423  47u/6.3V_8  [C0805]  244.42 134.99 0 top
C94424  47u/6.3V_8  [C0805]  247.72 135.02 180 top
C94425  47u/6.3V_8  [C0805]  244.42 137.02 0 top
C94426  47u/6.3V_8  [C0805]  247.72 137.18 180 top
C94432  1u/6.3V_2  [C0201]  246.53 121.66 0 bottom
C94433  1u/6.3V_2  [C0201]  243.23 126.1 0 bottom
C94434  1u/6.3V_2  [C0201]  243.23 118.48 0 bottom
C94435  1u/6.3V_2  [C0201]  233.32 112.61 270 bottom
C94436  1u/6.3V_2  [C0201]  243.23 117.72 0 bottom
C94437  1u/6.3V_2  [C0201]  236.01 114.44 180 bottom
C94438  1u/6.3V_2  [C0201]  243.23 115.43 0 bottom
C94439  1u/6.3V_2  [C0201]  243.23 124.58 0 bottom
C94440  1u/6.3V_2  [C0201]  241.19 124.25 180 bottom
C94441  1u/6.3V_2  [C0201]  244.88 114.77 180 bottom
C94442  1u/6.3V_2  [C0201]  243.23 125.34 0 bottom
C94443  1u/6.3V_2  [C0201]  241.19 124.96 180 bottom
C94444  1u/6.3V_2  [C0201]  246.53 122.42 0 bottom
C94445  1u/6.3V_2  [C0201]  246.53 114.8 0 bottom
C94446  1u/6.3V_2  [C0201]  244.88 121.63 180 bottom
C94447  1u/6.3V_2  [C0201]  246.53 126.99 0 bottom
C94448  1u/6.3V_2  [C0201]  246.53 113.25 0 bottom
C94449  1u/6.3V_2  [C0201]  241.19 126.48 180 bottom
C94450  1u/6.3V_2  [C0201]  236.04 113.71 180 bottom
C94451  1u/6.3V_2  [C0201]  246.53 118.61 0 bottom
C94452  1u/6.3V_2  [C0201]  246.53 124.71 0 bottom
C94453  1u/6.3V_2  [C0201]  243.23 122.29 0 bottom
C94454  1u/6.3V_2  [C0201]  246.53 116.32 0 bottom
C94455  1u/6.3V_2  [C0201]  236.04 113 180 bottom
C94456  1u/6.3V_2  [C0201]  244.88 117.06 180 bottom
C94457  1u/6.3V_2  [C0201]  244.88 116.3 180 bottom
C94458  1u/6.3V_2  [C0201]  241.19 123.49 180 bottom
C94459  1u/6.3V_2  [C0201]  246.53 120.9 0 bottom
C94460  1u/6.3V_2  [C0201]  243.23 120.77 0 bottom
C94461  1u/6.3V_2  [C0201]  246.53 117.85 0 bottom
C94462  1u/6.3V_2  [C0201]  243.23 123.05 0 bottom
C94463  1u/6.3V_2  [C0201]  243.23 116.96 0 bottom
C94464  1u/6.3V_2  [C0201]  244.88 118.58 180 bottom
C94465  1u/6.3V_2  [C0201]  244.88 123.94 180 bottom
C94466  1u/6.3V_2  [C0201]  244.88 123.16 180 bottom
C94467  1u/6.3V_2  [C0201]  243.23 119.24 0 bottom
C94468  1u/6.3V_2  [C0201]  244.88 120.11 180 bottom
C94469  1u/6.3V_2  [C0201]  243.23 120.01 0 bottom
C94470  1u/6.3V_2  [C0201]  246.53 123.18 0 bottom
C94471  1u/6.3V_2  [C0201]  246.53 117.09 0 bottom
C94472  1u/6.3V_2  [C0201]  246.53 114.04 0 bottom
C94473  1u/6.3V_2  [C0201]  244.88 120.87 180 bottom
C94474  1u/6.3V_2  [C0201]  244.88 117.82 180 bottom
C94475  1u/6.3V_2  [C0201]  243.23 113.91 0 bottom
C94476  1u/6.3V_2  [C0201]  241.19 125.72 180 bottom
C94477  1u/6.3V_2  [C0201]  244.88 115.54 180 bottom
C94478  1u/6.3V_2  [C0201]  244.88 119.35 180 bottom
C94479  1u/6.3V_2  [C0201]  246.53 125.47 0 bottom
C94480  1u/6.3V_2  [C0201]  243.23 123.82 0 bottom
C94481  1u/6.3V_2  [C0201]  246.53 115.56 0 bottom
C94482  1u/6.3V_2  [C0201]  244.88 122.39 180 bottom
C94483  1u/6.3V_2  [C0201]  246.53 123.94 0 bottom
C94484  1u/6.3V_2  [C0201]  244.88 113.2 180 bottom
C94485  1u/6.3V_2  [C0201]  241.19 122.72 180 bottom
C94486  1u/6.3V_2  [C0201]  244.88 114.01 180 bottom
C94487  1u/6.3V_2  [C0201]  244.88 124.71 180 bottom
C94488  1u/6.3V_2  [C0201]  246.53 126.23 0 bottom
C94489  1u/6.3V_2  [C0201]  243.23 121.53 0 bottom
C94490  1u/6.3V_2  [C0201]  243.23 116.2 0 bottom
C94491  1u/6.3V_2  [C0201]  244.88 125.44 180 bottom
C94492  1u/6.3V_2  [C0201]  243.23 114.67 0 bottom
C94493  1u/6.3V_2  [C0201]  246.53 119.37 0 bottom
C94494  1u/6.3V_2  [C0201]  246.53 120.13 0 bottom
C94495  47u/6.3V_8  [C0805]  217.95 138.52 90 top
C94496  47u/6.3V_8  [C0805]  215.92 138.52 90 top
C94497  10u/6.3V_4  [C0402_2]  232 117.19 180 bottom
C94498  10u/6.3V_4  [C0402_2]  245.05 112.16 180 bottom
C94499  10u/6.3V_4  [C0402_2]  232 115.92 180 bottom
C94504  1u/6.3V_2  [C0201]  224.3 138.93 180 bottom
C94505  1u/6.3V_2  [C0201]  224.3 138.04 180 bottom
C94506  1u/6.3V_2  [C0201]  224.3 139.82 180 bottom
C94507  10u/6.3V_4  [C0402_2]  228.75 143.09 180 bottom
C94508  10u/6.3V_4  [C0402_2]  231.8 140.55 270 bottom
C94509  10u/6.3V_4  [C0402_2]  232.18 125.31 90 bottom
C94510  10u/6.3V_4  [C0402_2]  230.4 140.55 270 bottom
C94511  10u/6.3V_4  [C0402_2]  224.3 140.94 0 bottom
C94512  10u/6.3V_4  [C0402_2]  228.75 141.82 180 bottom
C94513  10u/6.3V_4  [C0402_2]  228.75 140.55 180 bottom
C94518  47u/6.3V_8  [C0805]  225.07 136.27 0 top
C94519  47u/6.3V_8  [C0805]  230.93 134.73 180 top
C94521  22u/6.3V_4  [C0402_2]  223.72 95.57 180 bottom
C94522  22u/6.3V_6  [C0603]  249.5 112.67 270 bottom
C94523  22u/6.3V_6  [C0603]  256.28 112.08 180 bottom
C94524  22u/6.3V_6  [C0603]  242.82 112.11 180 bottom
C94525  10u/6.3V_4  [C0402_2]  223.95 94.25 180 bottom
C94526  10u/6.3V_4  [C0402_2]  232.07 111.93 180 bottom
C94527  10u/6.3V_4  [C0402_2]  231.49 56.63 0 bottom
C94528  10u/6.3V_4  [C0402_2]  252.17 111.78 180 bottom
C94529  10u/6.3V_4  [C0402_2]  226.61 94.05 0 bottom
C94530  10u/6.3V_4  [C0402_2]  247.67 112.08 180 bottom
C94531  *47u/6.3V_6  [C0603]  205.51 86.17 90 top
C94532  *47u/6.3V_6  [C0603]  207.59 92.96 270 top
C94533  *47u/6.3V_6  [C0603]  204.62 92.98 270 top
C94534  *47u/6.3V_6  [C0603]  206.04 92.98 270 top
C94535  10u/6.3V_4  [C0402_2]  236.37 111.98 0 bottom
C94536  1u/6.3V_2  [C0201]  261.13 112.61 270 bottom
C94537  1u/6.3V_2  [C0201]  262.15 112.61 270 bottom
C94539  1u/6.3V_2  [C0201]  230.27 124.55 0 bottom
C94542  0.1u/10V_2  [C0201]  336.62 60.67 90 top
C94543  0.1u/10V_2  [C0201]  330.47 52.67 180 top
C94544  0.1u/10V_2  [C0201]  333.12 60.5 180 top
C94545  0.1u/10V_2  [C0201]  336.95 51.53 0 top
C94547  *1u/6.3V_2  [C0201]  333.27 61.23 180 top
C94548  0.1u/10V_2  [C0201]  330.32 57.75 0 top
C94549  0.1u/10V_2  [C0201]  329.08 54.7 0 top
C94550  0.1u/10V_2  [C0201]  329.08 53.94 0 top
C94551  0.1u/10V_2  [C0201]  330.32 56.1 0 top
C94552  0.1u/10V_2  [C0201]  330.32 55.34 0 top
C94553  0.1u/10V_2  [C0201]  329.08 57.24 0 top
C94554  0.1u/10V_2  [C0201]  329.08 56.48 0 top
C94555  0.1u/10V_2  [C0201]  334.03 48.61 90 top
C94556  0.1u/10V_2  [C0201]  335.3 48.61 90 top
C94559  0.1u/10V_2  [C0201]  341.78 55.34 180 top
C94560  0.1u/10V_2  [C0201]  340.63 54.88 180 top
C94561  0.1u/10V_2  [C0201]  340.63 54.17 180 top
C94562  0.1u/10V_2  [C0201]  341.78 52.98 180 top
C94563  0.1u/10V_2  [C0201]  341.78 53.74 180 top
C94564  0.1u/10V_2  [C0201]  340.63 51.78 180 top
C94565  0.1u/10V_2  [C0201]  340.63 52.54 180 top
C94566  0.1u/10V_2  [C0201]  342.03 55.08 180 bottom
C94567  0.1u/10V_2  [C0201]  342.03 54.32 180 bottom
C94568  0.1u/10V_2  [C0201]  345.59 50.99 180 bottom
C94569  0.1u/10V_2  [C0201]  345.59 50.23 180 bottom
C94570  0.22u/6.3V_2  [C0201]  357.91 50.64 180 bottom
C94571  0.22u/6.3V_2  [C0201]  357.93 50.33 180 top
C94572  0.22u/6.3V_2  [C0201]  357.93 49.57 180 top
C94573  0.22u/6.3V_2  [C0201]  344.83 45.43 180 top
C94574  0.22u/6.3V_2  [C0201]  344.83 44.72 180 top
C94575  0.22u/6.3V_2  [C0201]  348.18 45.15 270 top
C94576  0.22u/6.3V_2  [C0201]  348.94 45.15 270 top
C94577  0.22u/6.3V_2  [C0201]  350.67 45.3 270 top
C94578  0.22u/6.3V_2  [C0201]  349.88 45.3 270 top
C94579  0.22u/6.3V_2  [C0201]  351.56 44.92 270 top
C94580  0.22u/6.3V_2  [C0201]  352.32 44.92 270 top
C94581  10p/50V_4  [C0402]  353.59 45.33 180 top
C94582  1u/6.3V_2  [C0201]  350.41 55.06 90 bottom
C94583  1u/6.3V_2  [C0201]  345.08 52.29 0 bottom
C94584  1u/6.3V_2  [C0201]  350.41 53.05 90 bottom
C94585  1u/6.3V_2  [C0201]  350.41 56.05 270 bottom
C94586  1u/6.3V_2  [C0201]  350.41 54.04 90 bottom
C94588  1u/6.3V_2  [C0201]  345.08 53.05 0 bottom
C94589  1u/6.3V_2  [C0201]  349.65 48.3 90 bottom
C94590  1u/6.3V_2  [C0201]  350.54 48.3 90 bottom
C94591  1u/6.3V_2  [C0201]  348.89 48.3 90 bottom
C94592  1u/6.3V_2  [C0201]  351.3 48.3 90 bottom
C94593  1u/6.3V_2  [C0201]  347.75 50.79 0 bottom
C94594  1u/6.3V_2  [C0201]  348.99 51.4 270 bottom
C94595  1u/6.3V_2  [C0201]  349.14 54.42 270 bottom
C94596  1u/6.3V_2  [C0201]  349.14 53.43 90 bottom
C94598  1u/6.3V_2  [C0201]  349.14 55.42 90 bottom
C94599  1u/6.3V_2  [C0201]  351.12 50.51 90 bottom
C94600  1u/6.3V_2  [C0201]  354.48 55.97 180 bottom
C94601  1u/6.3V_2  [C0201]  341.27 56.23 90 bottom
C94602  1u/6.3V_2  [C0201]  357.65 60.8 90 top
C94603  10u/6.3V_4  [C0402_2]  359.94 60.93 90 top
C94604  10u/6.3V_4  [C0402_2]  359.94 58.77 270 top
C94605  10u/6.3V_4  [C0402_2]  358.67 58.77 270 top
C94606  1u/6.3V_2  [C0201]  354.48 52.16 180 bottom
C94607  1u/6.3V_2  [C0201]  354.48 55.21 180 bottom
C94608  1u/6.3V_2  [C0201]  354.48 52.92 180 bottom
C94609  1u/6.3V_2  [C0201]  354.48 54.45 180 bottom
C94610  1u/6.3V_2  [C0201]  352.57 52.8 0 bottom
C94611  1u/6.3V_2  [C0201]  354.48 53.69 180 bottom
C94612  1u/6.3V_2  [C0201]  352.88 54.19 180 bottom
C94613  47u/6.3V_6  [C0603]  354.2 65.17 270 top
C94614  47u/6.3V_6  [C0603]  355.62 65.17 270 top
C94615  10u/6.3V_4  [C0402_2]  354.71 49.62 0 bottom
C94616  10u/6.3V_4  [C0402_2]  354.71 50.89 0 bottom
C94617  1u/6.3V_2  [C0201]  351.68 51.65 90 bottom
C94618  1u/6.3V_2  [C0201]  351.68 52.67 270 bottom
C94624  0.47u/25V_4  [C0402]  381.53 41.75 90 bottom
C94625  0.47u/25V_4  [C0402]  382.54 45.3 270 bottom
C94626  0.47u/25V_4  [C0402]  381.53 45.3 270 bottom
C94630  *SUB@680p/50V_4  [C0402]  32.58 38.09 0 bottom
C94631  *SUB@680p/50V_4  [C0402]  30.75 37.23 0 bottom
C94632  *SUB@680p/50V_4  [C0402]  31.03 39.23 0 bottom
C94633  *0.1u/10V_2  [C0201]  173.25 70.58 180 top
C94634  0.1u/10V_2  [C0201]  181.78 67.3 90 bottom
C94635  0.1u/10V_2  [C0201]  185.82 67.02 90 bottom
C94636  0.1u/10V_2  [C0201]  186.71 67.02 90 bottom
C94637  0.1u/10V_2  [C0201]  193.82 63.85 0 bottom
C94638  0.1u/10V_2  [C0201]  186.33 53.69 180 bottom
C94639  0.1u/10V_2  [C0201]  186.33 54.4 180 bottom
C94640  0.1u/10V_2  [C0201]  178.58 55.46 180 bottom
C94641  0.1u/10V_2  [C0201]  192.17 57.37 90 bottom
C94642  0.1u/10V_2  [C0201]  180.87 69.56 90 top
C94643  180p/50V_4  [C0402]  192.17 67.15 270 bottom
C94644  180p/50V_4  [C0402]  183.81 67.15 90 bottom
C94645  180p/50V_4  [C0402]  193.95 53.81 180 bottom
C94646  180p/50V_4  [C0402]  178.71 69.94 270 top
C94647  DIS@0.1u/10V_2  [C0201]  335.71 71.7 90 bottom
C94648  DIS@0.1u/10V_2  [C0201]  336.21 78.83 0 top
C94649  DIS@0.1u/10V_2  [C0201]  333.01 78.86 90 top
C94650  *DIS@1u/6.3V_2  [C0201]  332.25 78.81 90 top
C94652  DIS@0.1u/10V_2  [C0201]  332.51 72.36 0 bottom
C94655  DIS@0.1u/10V_2  [C0201]  330.35 77.56 0 top
C94656  DIS@0.1u/10V_2  [C0201]  330.35 72.61 0 top
C94657  DIS@0.1u/10V_2  [C0201]  330.35 71.85 0 top
C94658  DIS@10u/6.3V_4  [C0402_2]  335.81 80.1 270 top
C94659  DIS@0.1u/10V_2  [C0201]  330.35 76.8 0 top
C94668  DIS@0.1u/10V_2  [C0201]  330.35 74.26 0 top
C94669  DIS@0.1u/10V_2  [C0201]  330.35 73.5 0 top
C94670  DIS@0.1u/10V_2  [C0201]  330.35 75.91 0 top
C94671  DIS@0.1u/10V_2  [C0201]  330.35 75.15 0 top
C94676  DIS@0.1u/10V_2  [C0201]  342.16 77.94 90 top
C94677  DIS@0.1u/10V_2  [C0201]  342.92 77.94 90 top
C94678  OP@0.1u/10V_2  [C0201]  342.16 80.99 270 bottom
C94679  OP@0.1u/10V_2  [C0201]  342.92 80.99 270 bottom
C94680  0.1u/10V_2  [C0201]  340.13 77.82 90 top
C94681  1000p/50V_4  [C0402]  339.24 77.94 270 top
C94682  0.1u/10V_2  [C0201]  356.64 78.96 0 top
C94683  1000p/50V_4  [C0402]  357.53 80.1 0 bottom
C94684  DIS@0.1u/10V_2  [C0201]  343.68 77.94 90 top
C94685  OP@0.1u/10V_2  [C0201]  343.68 80.99 270 bottom
C94686  OP@0.1u/10V_2  [C0201]  344.44 80.99 270 bottom
C94688  DIS@0.1u/10V_2  [C0201]  344.44 77.94 90 top
C94689  DIS@0.1u/10V_2  [C0201]  345.21 77.94 90 top
C94690  DIS@0.1u/10V_2  [C0201]  345.97 77.94 90 top
C94691  OP@0.1u/10V_2  [C0201]  345.21 80.99 270 bottom
C94692  OP@0.1u/10V_2  [C0201]  345.97 80.99 270 bottom
C94693  DIS@0.1u/10V_2  [C0201]  346.73 77.94 90 top
C94694  DIS@0.1u/10V_2  [C0201]  347.49 77.94 90 top
C94695  OP@0.1u/10V_2  [C0201]  346.73 80.99 270 bottom
C94696  OP@0.1u/10V_2  [C0201]  347.49 80.99 270 bottom
C94697  DIS@0.1u/10V_2  [C0201]  341.4 78.32 90 bottom
C94698  DIS@0.1u/10V_2  [C0201]  340.51 78.32 90 bottom
C94699  OP@0.1u/10V_2  [C0201]  341.37 82.62 180 bottom
C94700  OP@0.1u/10V_2  [C0201]  340.28 82.62 0 bottom
C94701  22u/25V_8  [C0805]  334.03 80.99 90 top
C94702  1000p/50V_4  [C0402]  359.18 79.21 0 top
C94703  0.1u/10V_2  [C0201]  355.37 78.96 0 top
C94704  1000p/50V_4  [C0402]  356.26 78.32 270 bottom
C94705  1u/6.3V_2  [C0201]  326.16 71.47 90 top
C94707  *2.2u/10V_4  [C0402]  328.57 75.66 90 top
C94708  0.1u/10V_2  [C0201]  326.92 75.66 270 top
C94709  0.01u/50V_4  [C0402]  327.17 73.63 90 top
C94710  10u/6.3V_4  [C0402_2]  328.32 73.63 90 top
C94711  4.7u/6.3V_4  [C0402_2]  238.4 167.35 270 top
C94718  10u/6.3V_4  [C0402_2]  259.74 172.3 180 top
C94719  0.1u/10V_2  [C0201]  241.57 168.11 270 top
C94720  0.1u/10V_2  [C0201]  247.82 168.11 90 top
C94721  0.1u/10V_2  [C0201]  248.94 168.11 90 top
C94723  0.1u/10V_2  [C0201]  257.83 168.37 90 top
C94724  0.1u/10V_2  [C0201]  259.74 171.16 0 top
C94725  0.1u/10V_2  [C0201]  255.04 163.92 90 top
C94726  0.1u/10V_2  [C0201]  240.69 168.11 270 top
C94735  0.1u/10V_2  [C0201]  245.61 168.09 270 top
C94736  0.1u/10V_2  [C0201]  246.78 168.11 270 top
C94737  0.1u/10V_2  [C0201]  243.25 168.11 270 top
C94738  0.1u/10V_2  [C0201]  244.37 168.11 270 top
C94739  0.01u/50V_4  [C0402]  246.7 165.32 0 top
C94740  0.1u/10V_2  [C0201]  251.23 164.05 270 top
C94741  0.01u/50V_4  [C0402]  249.58 165.32 0 top
C94742  0.1u/10V_2  [C0201]  248.31 163.8 270 top
C94743  0.1u/10V_2  [C0201]  223.92 166.39 90 top
C94744  0.1u/10V_2  [C0201]  220.49 166.39 90 top
C94747  0.1u/10V_2  [C0201]  218.08 166.39 90 top
C94748  0.1u/10V_2  [C0201]  218.84 166.39 90 top
C94749  0.1u/10V_2  [C0201]  225.45 166.39 90 top
C94750  0.1u/10V_2  [C0201]  226.33 166.39 90 top
C94751  0.1u/10V_2  [C0201]  223.03 166.39 90 top
C94754  0.1u/10V_2  [C0201]  221.25 166.39 90 top
C94764  *220p/50V_4  [C0402]  231.8 170.4 180 top
C94765  220p/50V_4  [C0402]  231.03 170.15 90 bottom
C94774  *2200p/50V_4  [C0402]  359.48 45.18 180 bottom
C94775  *P_KB@220p/50V_8P4C  [8P4R]  224.05 51.65 180 bottom
C94776  P_PB@0.1u/10V_2  [C0201]  180.47 49.95 0 top
C94777  *P_KB@220p/50V_8P4C  [8P4R]  206.01 51.65 180 bottom
C94778  P_PB@180p/50V_4  [C0402]  175.03 58.64 90 top
C94780  *P_KB@220p/50V_8P4C  [8P4R]  209.82 51.65 180 bottom
C94781  *P_KB@220p/50V_8P4C  [8P4R]  213.89 51.65 180 bottom
C94782  *P_KB@220p/50V_8P4C  [8P4R]  227.99 51.65 180 bottom
C94783  *P_KB@220p/50V_8P4C  [8P4R]  218.08 51.65 180 bottom
C94784  P_KB@2.2u/10V_4  [C0402]  254.99 51.02 0 bottom
C94785  *0.1u/10V_2  [C0201]  131.21 67.28 0 top
C94786  0.1u/10V_2  [C0201]  132.86 62.83 0 top
C94787  0.1u/10V_2  [C0201]  132.86 63.59 0 top
C94788  **1000p/50V_4  [C0402]  134.77 66.01 270 top
C94789  *P_TP@1000p/50V_4  [C0402]  137.94 57.5 180 bottom
C94790  *P_TP@1000p/50V_4  [C0402]  139.72 57.5 0 bottom
C94791  0.01u/50V_4  [C0402]  138.45 60.04 180 bottom
C94796  0.1u/10V_2  [C0201]  285.26 59.83 0 top
C94797  0.1u/10V_2  [C0201]  285.26 60.6 0 top
C94798  0.1u/10V_2  [C0201]  286.89 60.95 0 top
C94799  0.1u/10V_2  [C0201]  286.89 61.71 0 top
C94800  0.22u/6.3V_2  [C0201]  285.74 62.07 0 top
C94801  0.22u/6.3V_2  [C0201]  285.74 62.83 0 top
C94802  0.22u/6.3V_2  [C0201]  286.48 63.62 0 top
C94803  0.22u/6.3V_2  [C0201]  286.48 64.38 0 top
C94804  18p/50V_4  [C0402]  320.06 58.89 180 top
C94805  18p/50V_4  [C0402]  326.03 57.12 0 bottom
C94807  33p/50V_4  [C0402]  315.23 54.45 90 bottom
C94808  *0.1u/10V_2  [C0201]  324.51 57.73 0 top
C94809  *0.1u/10V_2  [C0201]  321.33 46.63 0 top
C94810  1u/6.3V_2  [C0201]  322.6 49.39 270 bottom
C94811  1u/6.3V_2  [C0201]  324.43 55.72 270 bottom
C94812  1u/6.3V_2  [C0201]  324.33 54.04 90 bottom
C94814  *220p/50V_4  [C0402]  315.11 57.5 90 bottom
C94815  *220p/50V_4  [C0402]  315.95 47.67 270 top
C94818  *0.1u/10V_2  [C0201]  296.34 81.98 90 bottom
C94819  15p/50V_4  [C0402]  318.49 52.62 270 top
C94820  27p/50V_4  [C0402]  287.93 56.53 90 top
C94821  15p/50V_4  [C0402]  318.49 54.4 90 top
C94822  27p/50V_4  [C0402]  287.93 52.72 270 top
C94823  0.1u/10V_2  [C0201]  329.38 47.84 180 top
C94824  0.1u/10V_2  [C0201]  324.76 67.53 90 bottom
C94828  1u/6.3V_2  [C0201]  307.03 64.05 180 bottom
C94829  *1u/6.3V_2  [C0201]  301.29 66.13 180 bottom
C94830  *1u/6.3V_2  [C0201]  310.15 64.1 0 bottom
C94831  0.1u/10V_2  [C0201]  313.84 73.37 90 bottom
C94832  1u/6.3V_2  [C0201]  310.38 66.11 270 bottom
C94833  0.1u/10V_2  [C0201]  307.11 74.13 0 bottom
C94834  0.1u/10V_2  [C0201]  300.1 74.11 0 bottom
C94835  0.1u/10V_2  [C0201]  307.87 54.45 180 bottom
C94836  22u/6.3V_4  [C0402_2]  306.6 60.7 180 bottom
C94837  22u/6.3V_4  [C0402_2]  302.53 68.93 180 bottom
C94838  *1u/6.3V_2  [C0201]  297.25 49.65 0 bottom
C94839  0.1u/10V_2  [C0201]  311.7 66.51 0 bottom
C94840  1u/6.3V_2  [C0201]  299.74 65.5 0 bottom
C94841  0.1u/10V_2  [C0201]  305.15 64.71 0 bottom
C94842  22u/6.3V_4  [C0402_2]  298.09 66.46 270 bottom
C94843  1u/6.3V_2  [C0201]  287.9 74.44 180 top
C94844  1u/6.3V_2  [C0201]  292.42 77.51 0 top
C94845  1u/6.3V_2  [C0201]  302.05 59.68 270 bottom
C94846  1u/6.3V_2  [C0201]  311.7 59.81 90 bottom
C94847  *1u/6.3V_2  [C0201]  315.56 49.47 270 top
C94848  1u/6.3V_2  [C0201]  300.63 58.77 180 bottom
C94850  1u/6.3V_2  [C0201]  313.15 63.75 270 bottom
C94851  0.1u/10V_2  [C0201]  312.39 63.75 270 bottom
C94852  1u/6.3V_2  [C0201]  311.86 60.85 90 bottom
C94853  0.1u/10V_2  [C0201]  311.78 61.92 270 bottom
C94854  1u/6.3V_2  [C0201]  303.96 54.14 180 bottom
C94855  0.1u/10V_2  [C0201]  318.66 47.84 270 bottom
C94859  2.2u/10V_4  [C0402]  212.59 63.59 180 bottom
C94860  0.1u/10V_2  [C0201]  212.59 62.73 0 bottom
C94861  *0.1u/10V_2  [C0201]  251.3 66.51 90 bottom
C94862  1u/6.3V_2  [C0201]  242.59 61.48 270 bottom
C94863  0.1u/10V_2  [C0201]  234.69 54.09 0 bottom
C94864  1u/6.3V_2  [C0201]  207.97 58.23 180 bottom
C94865  1u/6.3V_2  [C0201]  259.3 61.92 180 bottom
C94866  2.2u/10V_4  [C0402]  234.72 53.26 0 bottom
C94867  1u/6.3V_2  [C0201]  207.97 56.58 180 bottom
C94868  1u/6.3V_2  [C0201]  239.03 62.07 0 bottom
C94869  1u/6.3V_2  [C0201]  207.97 55.74 180 bottom
C94870  1u/6.3V_2  [C0201]  234.03 63.75 180 bottom
C94871  1u/6.3V_2  [C0201]  207.97 57.4 180 bottom
C94872  1u/6.3V_2  [C0201]  221.71 54.19 0 bottom
C94873  1u/6.3V_2  [C0201]  210.97 60.8 90 bottom
C94874  10u/6.3V_4  [C0402_2]  207.94 59.22 0 bottom
C94875  1u/6.3V_2  [C0201]  242.44 66.51 90 bottom
C94876  10u/6.3V_4  [C0402_2]  210 60.72 90 bottom
C94877  1u/6.3V_2  [C0201]  248.97 61.46 270 bottom
C94879  1u/6.3V_2  [C0201]  235.99 64.28 180 bottom
C94881  10u/6.3V_4  [C0402_2]  273.88 54.55 0 bottom
C94882  10u/6.3V_4  [C0402_2]  247.95 56.07 270 bottom
C94883  10u/6.3V_4  [C0402_2]  245 61.69 90 bottom
C94884  10u/6.3V_4  [C0402_2]  226.92 61.81 180 bottom
C94885  10u/6.3V_4  [C0402_2]  216.78 61.92 180 bottom
C94886  10u/6.3V_4  [C0402_2]  265.25 55.92 270 bottom
C94887  10u/6.3V_4  [C0402_2]  250.13 57.34 90 bottom
C94888  10u/6.3V_4  [C0402_2]  243.68 61.71 90 bottom
C94889  0.022u/50V_4  [C0402]  239.44 52.09 180 bottom
C94890  0.1u/10V_2  [C0201]  212.06 74.16 270 bottom
C94891  2.2u/10V_4  [C0402]  211.2 74.08 270 bottom
C94892  *0.1u/10V_2  [C0201]  251.43 53.94 270 bottom
C94893  1u/6.3V_2  [C0201]  237.84 74.85 270 bottom
C94894  1u/6.3V_2  [C0201]  207.97 63.57 180 bottom
C94895  1u/6.3V_2  [C0201]  250.08 66.51 90 bottom
C94896  1u/6.3V_2  [C0201]  207.97 61.41 180 bottom
C94897  1u/6.3V_2  [C0201]  247.59 74.9 270 bottom
C94898  1u/6.3V_2  [C0201]  207.97 62.12 180 bottom
C94899  1u/6.3V_2  [C0201]  248.38 66.51 90 bottom
C94900  1u/6.3V_2  [C0201]  207.97 62.83 180 bottom
C94901  1u/6.3V_2  [C0201]  243.25 66.51 90 bottom
C94902  10u/6.3V_4  [C0402_2]  207.94 60.42 0 bottom
C94903  1u/6.3V_2  [C0201]  242.56 74.74 270 bottom
C94904  1u/6.3V_2  [C0201]  245.33 74.87 270 bottom
C94905  1u/6.3V_2  [C0201]  248.46 74.9 270 bottom
C94906  0.1u/10V_2  [C0201]  235.22 66.31 270 bottom
C94907  10u/6.3V_4  [C0402_2]  264.36 66.31 0 bottom
C94908  2.2u/10V_4  [C0402]  237.08 66.26 270 bottom
C94909  10u/6.3V_4  [C0402_2]  275.84 66.41 180 bottom
C94910  10u/6.3V_4  [C0402_2]  243.86 74.77 90 bottom
C94911  1u/6.3V_2  [C0201]  211.73 60.8 90 bottom
C94912  10u/6.3V_4  [C0402_2]  246.4 74.77 90 bottom
C94913  10u/6.3V_4  [C0402_2]  212.69 60.7 90 bottom
